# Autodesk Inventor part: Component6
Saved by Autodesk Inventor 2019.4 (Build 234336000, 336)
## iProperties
Created: 2020-06
Part Number: Component6
Material: Generic
Document SubType Name: Modeling
Designer: Administrator
Density: 1 g/cm^3
Appearance: Default
Title: Component6
Author: Administrator
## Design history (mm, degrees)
